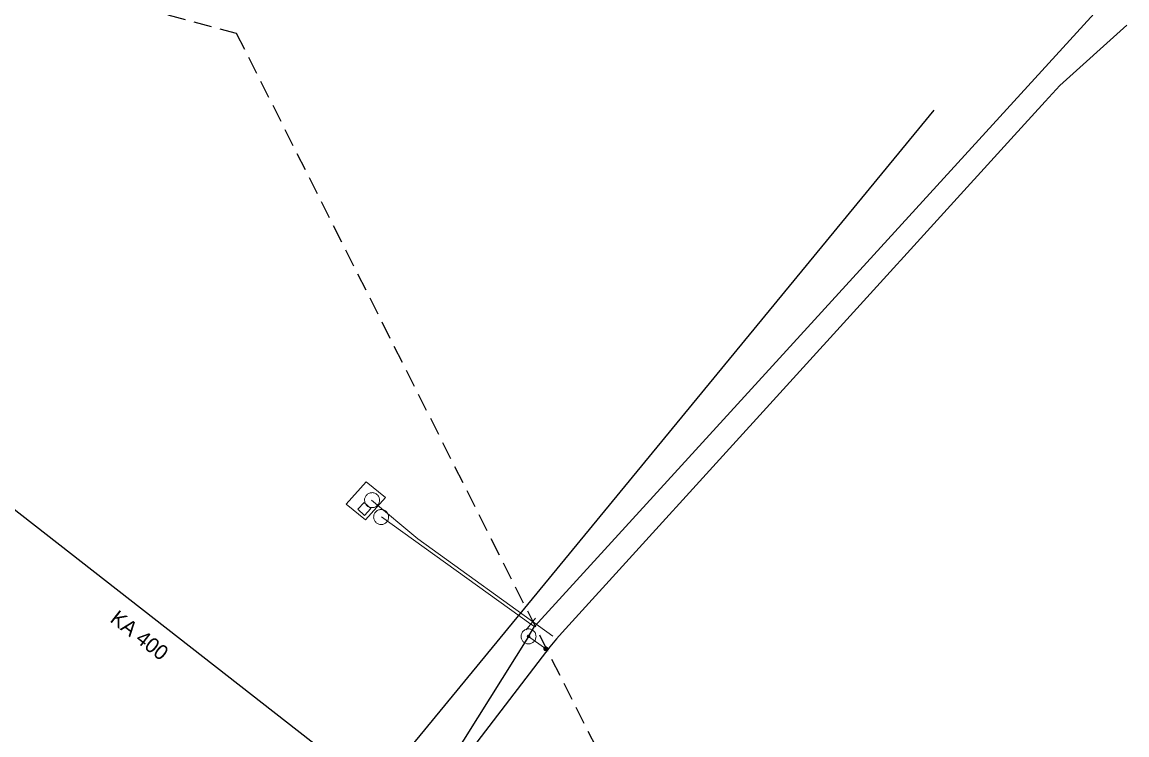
# Model space of a CAD drawing. Extents: x -790267 to -789874, y -989766 to -989454.
# Drawn here: x -789961.1 to -789887.3, y -989606.4 to -989558.8 of the extents above; entities that cross this region are included whole.
import ezdxf

# ---------------------------------------------------------------- set-up
doc = ezdxf.new("R2010")
doc.units = 0
doc.header["$LTSCALE"] = 0.4
doc.linetypes.add('MEDIUM_DASHED', pattern=[4.5, 3, -1.5])
doc.layers.add('1', color=7, linetype='Continuous')
for name, color, linetype, lineweight in [('13', 7, 'Continuous', 13), ('14', 7, 'Continuous', 13), ('17', 7, 'Continuous', 25), ('2', 7, 'Continuous', 13), ('23', 7, 'Continuous', 13), ('34', 7, 'Continuous', 13), ('47', 7, 'Continuous', 13), ('63', 7, 'MEDIUM_DASHED', 25), ('9', 7, 'Continuous', 13)]:
    doc.layers.add(name, color=color, linetype=linetype, lineweight=lineweight)

msp = doc.modelspace()

# ---------------------------------------------------------------- linework, layer by layer
at = {"layer": '13'}
msp.add_line((-789927.077, -989598.989), (-789937.049, -989591.839), dxfattribs=at)
msp.add_lwpolyline([(-789925.609, -989599.789), (-789934.62, -989593.289), (-789937.719, -989590.719)], dxfattribs=at)
at = {"layer": '14', "lineweight": 25}
for p, q in [((-789937.51, -989610.1), (-789900.16, -989564.68)), ((-789965.811, -989588.026), (-789937.51, -989610.1))]:
    msp.add_line(p, q, dxfattribs=at)
at = {"layer": '14'}
for p, q in [((-789926.833, -989599.162), (-789927.077, -989598.989)), ((-789927.239, -989599.813), (-789926.089, -989600.638))]:
    msp.add_line(p, q, dxfattribs=at)
at = {"layer": '17'}
msp.add_line((-789927.239, -989599.813), (-789932.749, -989608.579), dxfattribs=at)
for points in [[(-789927.239, -989599.813), (-789926.833, -989599.162), (-789888.3, -989556.917)], [(-789887.283, -989558.995), (-789891.77, -989563.02), (-789892.745, -989564.092), (-789895.041, -989566.616), (-789925, -989599.55), (-789925.366, -989599.978), (-789925.82, -989600.51), (-789931.5, -989607.92)]]:
    msp.add_lwpolyline(points, dxfattribs=at)
at = {"layer": '2'}
for points in [[(-789938.09, -989589.489), (-789939.42, -989590.98), (-789938.129, -989592.02), (-789936.794, -989590.53)], [(-789938.21, -989590.87), (-789938.629, -989591.309), (-789938.193, -989591.736), (-789937.76, -989591.28)]]:
    msp.add_lwpolyline(points, close=True, dxfattribs=at)
at = {"layer": '23'}
for points in [[(-789937.204, -989590.586), (-789937.219, -989590.537), (-789937.241, -989590.489), (-789937.266, -989590.444), (-789937.298, -989590.401), (-789937.333, -989590.363), (-789937.371, -989590.328), (-789937.414, -989590.298), (-789937.459, -989590.271), (-789937.507, -989590.249), (-789937.557, -989590.234), (-789937.608, -989590.222), (-789937.659, -989590.216), (-789937.712, -989590.218), (-789937.764, -989590.222), (-789937.815, -989590.233), (-789937.866, -989590.249), (-789937.913, -989590.27), (-789937.959, -989590.297), (-789938, -989590.328), (-789938.039, -989590.362), (-789938.075, -989590.401), (-789938.106, -989590.443), (-789938.132, -989590.489), (-789938.152, -989590.536), (-789938.169, -989590.586), (-789938.18, -989590.637), (-789938.185, -989590.69), (-789938.185, -989590.742), (-789938.179, -989590.793), (-789938.169, -989590.845), (-789938.153, -989590.894), (-789938.132, -989590.943), (-789938.105, -989590.989), (-789938.075, -989591.031), (-789938.04, -989591.068), (-789938.002, -989591.104), (-789937.958, -989591.135), (-789937.914, -989591.161), (-789937.864, -989591.183)], [(-789938.075, -989590.401), (-789938.106, -989590.443), (-789938.132, -989590.489), (-789938.152, -989590.536), (-789938.169, -989590.586), (-789938.18, -989590.637), (-789938.185, -989590.69), (-789938.185, -989590.742), (-789938.179, -989590.793), (-789938.169, -989590.845), (-789938.153, -989590.894), (-789938.132, -989590.943), (-789938.105, -989590.989), (-789938.075, -989591.031), (-789938.04, -989591.068), (-789938.002, -989591.104), (-789937.958, -989591.135), (-789937.914, -989591.161), (-789937.864, -989591.183), (-789937.817, -989591.199), (-789937.765, -989591.21), (-789937.712, -989591.215), (-789937.66, -989591.215), (-789937.607, -989591.209), (-789937.556, -989591.199), (-789937.507, -989591.183), (-789937.459, -989591.16), (-789937.414, -989591.135), (-789937.372, -989591.104), (-789937.333, -989591.068), (-789937.298, -989591.03), (-789937.267, -989590.988), (-789937.241, -989590.943), (-789937.219, -989590.894), (-789937.203, -989590.845), (-789937.193, -989590.795), (-789937.188, -989590.742), (-789937.187, -989590.69), (-789937.192, -989590.637), (-789937.204, -989590.586)], [(-789937.959, -989590.297), (-789938, -989590.328), (-789938.039, -989590.362), (-789938.075, -989590.401)], [(-789937.864, -989591.183), (-789937.817, -989591.199), (-789937.765, -989591.21), (-789937.712, -989591.215), (-789937.66, -989591.215), (-789937.607, -989591.209), (-789937.556, -989591.199), (-789937.507, -989591.183), (-789937.459, -989591.16), (-789937.414, -989591.135), (-789937.372, -989591.104), (-789937.333, -989591.068), (-789937.298, -989591.03), (-789937.267, -989590.988), (-789937.241, -989590.943), (-789937.219, -989590.894), (-789937.203, -989590.845), (-789937.193, -989590.795), (-789937.188, -989590.742), (-789937.187, -989590.69), (-789937.192, -989590.637), (-789937.204, -989590.586), (-789937.219, -989590.537), (-789937.241, -989590.489), (-789937.266, -989590.444), (-789937.298, -989590.401), (-789937.333, -989590.363), (-789937.371, -989590.328), (-789937.414, -989590.298), (-789937.459, -989590.271), (-789937.507, -989590.249), (-789937.557, -989590.234), (-789937.608, -989590.222), (-789937.659, -989590.216), (-789937.712, -989590.218), (-789937.764, -989590.222), (-789937.815, -989590.233), (-789937.866, -989590.249), (-789937.913, -989590.27), (-789937.959, -989590.297)], [(-789936.671, -989592.131), (-789936.643, -989592.086), (-789936.62, -989592.038), (-789936.603, -989591.99), (-789936.59, -989591.939), (-789936.583, -989591.888), (-789936.582, -989591.834), (-789936.585, -989591.783), (-789936.594, -989591.732), (-789936.608, -989591.681), (-789936.628, -989591.633), (-789936.652, -989591.586), (-789936.682, -989591.542), (-789936.715, -989591.502), (-789936.753, -989591.467), (-789936.793, -989591.434), (-789936.839, -989591.406), (-789936.885, -989591.383), (-789936.936, -989591.365), (-789936.984, -989591.352), (-789937.036, -989591.345), (-789937.09, -989591.344), (-789937.142, -989591.348), (-789937.194, -989591.357), (-789937.244, -989591.37), (-789937.292, -989591.39), (-789937.339, -989591.416), (-789937.381, -989591.444), (-789937.421, -989591.478), (-789937.457, -989591.516), (-789937.49, -989591.557), (-789937.518, -989591.601), (-789937.541, -989591.648), (-789937.559, -989591.698), (-789937.572, -989591.748), (-789937.578, -989591.799), (-789937.58, -989591.852), (-789937.577, -989591.904), (-789937.568, -989591.957), (-789937.553, -989592.007)], [(-789936.936, -989591.365), (-789936.984, -989591.352), (-789937.036, -989591.345), (-789937.09, -989591.344), (-789937.142, -989591.348), (-789937.194, -989591.357), (-789937.244, -989591.37), (-789937.292, -989591.39), (-789937.339, -989591.416), (-789937.381, -989591.444), (-789937.421, -989591.478), (-789937.457, -989591.516), (-789937.49, -989591.557), (-789937.518, -989591.601), (-789937.541, -989591.648), (-789937.559, -989591.698), (-789937.572, -989591.748), (-789937.578, -989591.799), (-789937.58, -989591.852), (-789937.577, -989591.904), (-789937.568, -989591.957), (-789937.553, -989592.007), (-789937.534, -989592.054), (-789937.509, -989592.101), (-789937.481, -989592.144), (-789937.445, -989592.184), (-789937.408, -989592.22), (-789937.368, -989592.253), (-789937.323, -989592.28), (-789937.276, -989592.303), (-789937.226, -989592.322), (-789937.176, -989592.334), (-789937.124, -989592.341), (-789937.072, -989592.344), (-789937.019, -989592.339), (-789936.968, -989592.331), (-789936.919, -989592.316), (-789936.869, -989592.297), (-789936.823, -989592.272), (-789936.779, -989592.242)], [(-789937.553, -989592.007), (-789937.534, -989592.054), (-789937.509, -989592.101), (-789937.481, -989592.144), (-789937.445, -989592.184), (-789937.408, -989592.22), (-789937.368, -989592.253), (-789937.323, -989592.28), (-789937.276, -989592.303), (-789937.226, -989592.322), (-789937.176, -989592.334), (-789937.124, -989592.341), (-789937.072, -989592.344), (-789937.019, -989592.339), (-789936.968, -989592.331), (-789936.919, -989592.316), (-789936.869, -989592.297), (-789936.823, -989592.272), (-789936.779, -989592.242), (-789936.74, -989592.208), (-789936.704, -989592.171), (-789936.671, -989592.131), (-789936.643, -989592.086), (-789936.62, -989592.038), (-789936.603, -989591.99), (-789936.59, -989591.939), (-789936.583, -989591.888), (-789936.582, -989591.834), (-789936.585, -989591.783), (-789936.594, -989591.732), (-789936.608, -989591.681), (-789936.628, -989591.633), (-789936.652, -989591.586), (-789936.682, -989591.542), (-789936.715, -989591.502), (-789936.753, -989591.467), (-789936.793, -989591.434), (-789936.839, -989591.406), (-789936.885, -989591.383), (-789936.936, -989591.365)], [(-789936.779, -989592.242), (-789936.74, -989592.208), (-789936.704, -989592.171), (-789936.671, -989592.131)]]:
    msp.add_lwpolyline(points, dxfattribs=at)
at = {"layer": '34'}
msp.add_line((-789926.768, -989598.595), (-789927.386, -989599.381), dxfattribs=at)
at = {"layer": '47'}
for points in [[(-789926.739, -989599.813), (-789926.742, -989599.761), (-789926.75, -989599.708), (-789926.764, -989599.659), (-789926.781, -989599.61), (-789926.806, -989599.563), (-789926.835, -989599.519), (-789926.867, -989599.478), (-789926.904, -989599.441), (-789926.945, -989599.409), (-789926.989, -989599.38), (-789927.036, -989599.355), (-789927.085, -989599.338), (-789927.134, -989599.324), (-789927.186, -989599.316), (-789927.239, -989599.313), (-789927.291, -989599.316), (-789927.343, -989599.324), (-789927.394, -989599.338), (-789927.441, -989599.355), (-789927.489, -989599.38), (-789927.532, -989599.409), (-789927.573, -989599.441), (-789927.61, -989599.478), (-789927.644, -989599.519), (-789927.671, -989599.563), (-789927.696, -989599.61), (-789927.715, -989599.659), (-789927.727, -989599.708), (-789927.735, -989599.761), (-789927.739, -989599.813), (-789927.735, -989599.865), (-789927.727, -989599.917), (-789927.715, -989599.968), (-789927.696, -989600.016), (-789927.671, -989600.063), (-789927.644, -989600.107), (-789927.61, -989600.147), (-789927.573, -989600.184), (-789927.532, -989600.218), (-789927.489, -989600.245), (-789927.441, -989600.27), (-789927.394, -989600.289), (-789927.343, -989600.301), (-789927.291, -989600.309), (-789927.239, -989600.313), (-789927.186, -989600.309), (-789927.134, -989600.301), (-789927.085, -989600.289), (-789927.036, -989600.27), (-789926.989, -989600.245), (-789926.945, -989600.218), (-789926.904, -989600.184), (-789926.867, -989600.147), (-789926.835, -989600.107), (-789926.806, -989600.063), (-789926.781, -989600.016), (-789926.764, -989599.968), (-789926.75, -989599.917), (-789926.742, -989599.865)], [(-789927.156, -989599.813), (-789927.156, -989599.804), (-789927.159, -989599.796), (-789927.161, -989599.788), (-789927.164, -989599.779), (-789927.168, -989599.772), (-789927.173, -989599.765), (-789927.178, -989599.757), (-789927.183, -989599.752), (-789927.191, -989599.747), (-789927.198, -989599.742), (-789927.205, -989599.738), (-789927.213, -989599.735), (-789927.222, -989599.733), (-789927.23, -989599.73), (-789927.239, -989599.73), (-789927.247, -989599.73), (-789927.255, -989599.733), (-789927.264, -989599.735), (-789927.272, -989599.738), (-789927.279, -989599.742), (-789927.286, -989599.747), (-789927.294, -989599.752), (-789927.299, -989599.757), (-789927.306, -989599.765), (-789927.309, -989599.772), (-789927.313, -989599.779), (-789927.316, -989599.788), (-789927.318, -989599.796), (-789927.321, -989599.804), (-789927.321, -989599.813), (-789927.321, -989599.821), (-789927.318, -989599.83), (-789927.316, -989599.838), (-789927.313, -989599.846), (-789927.309, -989599.853), (-789927.306, -989599.86), (-789927.299, -989599.868), (-789927.294, -989599.874), (-789927.286, -989599.88), (-789927.279, -989599.884), (-789927.272, -989599.887), (-789927.264, -989599.891), (-789927.255, -989599.892), (-789927.247, -989599.895), (-789927.239, -989599.895), (-789927.23, -989599.895), (-789927.222, -989599.892), (-789927.213, -989599.891), (-789927.205, -989599.887), (-789927.198, -989599.884), (-789927.191, -989599.88), (-789927.183, -989599.874), (-789927.178, -989599.868), (-789927.173, -989599.86), (-789927.168, -989599.853), (-789927.164, -989599.846), (-789927.161, -989599.838), (-789927.159, -989599.83), (-789927.156, -989599.821)]]:
    msp.add_lwpolyline(points, close=True, dxfattribs=at)
at = {"layer": '63'}
msp.add_lwpolyline([(-790188.469, -989455.136), (-790139.344, -989496.446), (-790139.344, -989496.446), (-790029.929, -989518.217), (-790029.929, -989518.217), (-789963.498, -989555.061), (-789963.498, -989555.061), (-789946.75, -989559.527), (-789946.75, -989559.527), (-789908.79, -989634.89), (-789908.79, -989634.89), (-790051.142, -989765.519), (-790051.142, -989765.519), (-790157.208, -989714.719), (-790157.208, -989714.719), (-790153.3, -989672.851), (-790153.3, -989672.851), (-790266.065, -989576.274), (-790266.065, -989576.274), (-790235.362, -989502.586), (-790235.362, -989502.586), (-790189.028, -989455.694), (-790189.028, -989455.694)], close=True, dxfattribs=at)
at = {"layer": '9'}
for points in [[(-789926.215, -989600.638), (-789926.215, -989600.651), (-789926.213, -989600.664), (-789926.21, -989600.677), (-789926.205, -989600.689), (-789926.199, -989600.701), (-789926.192, -989600.712), (-789926.184, -989600.722), (-789926.174, -989600.732), (-789926.164, -989600.74), (-789926.153, -989600.747), (-789926.141, -989600.753), (-789926.129, -989600.758), (-789926.116, -989600.761), (-789926.103, -989600.763), (-789926.09, -989600.765), (-789926.077, -989600.764), (-789926.064, -989600.762), (-789926.051, -989600.759), (-789926.039, -989600.754), (-789926.027, -989600.748), (-789926.016, -989600.741), (-789926.006, -989600.733), (-789925.996, -989600.723), (-789925.988, -989600.713), (-789925.981, -989600.702), (-789925.975, -989600.69), (-789925.97, -989600.678), (-789925.967, -989600.665), (-789925.965, -989600.652), (-789925.963, -989600.639), (-789925.964, -989600.626), (-789925.966, -989600.613), (-789925.969, -989600.6), (-789925.974, -989600.588), (-789925.98, -989600.576), (-789925.987, -989600.565), (-789925.995, -989600.555), (-789926.005, -989600.545), (-789926.015, -989600.537), (-789926.026, -989600.53), (-789926.038, -989600.524), (-789926.05, -989600.519), (-789926.063, -989600.516), (-789926.076, -989600.514), (-789926.089, -989600.513), (-789926.102, -989600.513), (-789926.115, -989600.515), (-789926.128, -989600.518), (-789926.14, -989600.523), (-789926.152, -989600.529), (-789926.163, -989600.536), (-789926.173, -989600.544), (-789926.183, -989600.554), (-789926.191, -989600.564), (-789926.198, -989600.575), (-789926.204, -989600.587), (-789926.209, -989600.599), (-789926.212, -989600.612), (-789926.214, -989600.625)], [(-789926.195, -989600.638), (-789926.196, -989600.649), (-789926.194, -989600.66), (-789926.191, -989600.671), (-789926.187, -989600.681), (-789926.182, -989600.691), (-789926.176, -989600.7), (-789926.169, -989600.709), (-789926.161, -989600.717), (-789926.152, -989600.724), (-789926.143, -989600.73), (-789926.133, -989600.735), (-789926.123, -989600.739), (-789926.112, -989600.742), (-789926.101, -989600.745), (-789926.09, -989600.745), (-789926.079, -989600.745), (-789926.068, -989600.743), (-789926.057, -989600.74), (-789926.047, -989600.736), (-789926.037, -989600.731), (-789926.028, -989600.725), (-789926.019, -989600.718), (-789926.011, -989600.71), (-789926.004, -989600.701), (-789925.998, -989600.692), (-789925.993, -989600.682), (-789925.989, -989600.672), (-789925.986, -989600.661), (-789925.984, -989600.65), (-789925.983, -989600.639), (-789925.983, -989600.628), (-789925.985, -989600.617), (-789925.988, -989600.606), (-789925.992, -989600.596), (-789925.997, -989600.586), (-789926.003, -989600.577), (-789926.01, -989600.568), (-789926.018, -989600.56), (-789926.027, -989600.553), (-789926.036, -989600.547), (-789926.046, -989600.542), (-789926.056, -989600.538), (-789926.067, -989600.535), (-789926.078, -989600.533), (-789926.089, -989600.533), (-789926.1, -989600.532), (-789926.111, -989600.534), (-789926.122, -989600.537), (-789926.132, -989600.541), (-789926.142, -989600.546), (-789926.151, -989600.552), (-789926.16, -989600.559), (-789926.168, -989600.567), (-789926.175, -989600.576), (-789926.181, -989600.585), (-789926.186, -989600.595), (-789926.19, -989600.605), (-789926.193, -989600.616), (-789926.195, -989600.627)], [(-789926.176, -989600.638), (-789926.176, -989600.647), (-789926.175, -989600.656), (-789926.172, -989600.665), (-789926.169, -989600.673), (-789926.165, -989600.681), (-789926.16, -989600.689), (-789926.154, -989600.696), (-789926.148, -989600.702), (-789926.141, -989600.708), (-789926.133, -989600.713), (-789926.125, -989600.717), (-789926.117, -989600.72), (-789926.108, -989600.723), (-789926.099, -989600.724), (-789926.09, -989600.726), (-789926.081, -989600.725), (-789926.072, -989600.724), (-789926.063, -989600.721), (-789926.055, -989600.718), (-789926.047, -989600.714), (-789926.039, -989600.709), (-789926.032, -989600.703), (-789926.026, -989600.697), (-789926.02, -989600.69), (-789926.015, -989600.682), (-789926.011, -989600.674), (-789926.008, -989600.666), (-789926.005, -989600.657), (-789926.004, -989600.648), (-789926.002, -989600.639), (-789926.003, -989600.63), (-789926.004, -989600.621), (-789926.007, -989600.612), (-789926.01, -989600.604), (-789926.014, -989600.596), (-789926.019, -989600.588), (-789926.025, -989600.581), (-789926.031, -989600.575), (-789926.038, -989600.569), (-789926.046, -989600.564), (-789926.054, -989600.56), (-789926.062, -989600.557), (-789926.071, -989600.554), (-789926.08, -989600.553), (-789926.089, -989600.552), (-789926.098, -989600.552), (-789926.107, -989600.553), (-789926.116, -989600.556), (-789926.124, -989600.559), (-789926.132, -989600.563), (-789926.14, -989600.568), (-789926.147, -989600.574), (-789926.153, -989600.58), (-789926.159, -989600.587), (-789926.164, -989600.595), (-789926.168, -989600.603), (-789926.171, -989600.611), (-789926.174, -989600.62), (-789926.175, -989600.629)], [(-789926.156, -989600.638), (-789926.156, -989600.645), (-789926.155, -989600.652), (-789926.154, -989600.659), (-789926.151, -989600.665), (-789926.148, -989600.671), (-789926.144, -989600.677), (-789926.14, -989600.683), (-789926.135, -989600.688), (-789926.129, -989600.692), (-789926.123, -989600.696), (-789926.117, -989600.699), (-789926.111, -989600.702), (-789926.104, -989600.703), (-789926.097, -989600.706), (-789926.09, -989600.706), (-789926.083, -989600.706), (-789926.076, -989600.704), (-789926.069, -989600.703), (-789926.063, -989600.7), (-789926.056, -989600.697), (-789926.051, -989600.693), (-789926.045, -989600.689), (-789926.04, -989600.684), (-789926.036, -989600.678), (-789926.032, -989600.672), (-789926.029, -989600.666), (-789926.026, -989600.66), (-789926.024, -989600.653), (-789926.023, -989600.646), (-789926.022, -989600.639), (-789926.022, -989600.632), (-789926.023, -989600.625), (-789926.025, -989600.618), (-789926.028, -989600.612), (-789926.031, -989600.605), (-789926.035, -989600.6), (-789926.039, -989600.594), (-789926.044, -989600.589), (-789926.05, -989600.585), (-789926.055, -989600.581), (-789926.062, -989600.578), (-789926.068, -989600.575), (-789926.075, -989600.573), (-789926.082, -989600.572), (-789926.089, -989600.572), (-789926.096, -989600.572), (-789926.103, -989600.572), (-789926.11, -989600.574), (-789926.116, -989600.577), (-789926.122, -989600.58), (-789926.128, -989600.584), (-789926.134, -989600.588), (-789926.139, -989600.593), (-789926.143, -989600.599), (-789926.147, -989600.604), (-789926.15, -989600.611), (-789926.153, -989600.617), (-789926.154, -989600.624), (-789926.156, -989600.631)], [(-789926.136, -989600.638), (-789926.136, -989600.643), (-789926.136, -989600.648), (-789926.135, -989600.653), (-789926.133, -989600.657), (-789926.131, -989600.662), (-789926.128, -989600.666), (-789926.125, -989600.669), (-789926.121, -989600.673), (-789926.118, -989600.676), (-789926.114, -989600.679), (-789926.109, -989600.681), (-789926.105, -989600.683), (-789926.1, -989600.684), (-789926.095, -989600.686), (-789926.09, -989600.686), (-789926.085, -989600.686), (-789926.08, -989600.685), (-789926.075, -989600.684), (-789926.071, -989600.682), (-789926.066, -989600.68), (-789926.062, -989600.677), (-789926.058, -989600.674), (-789926.055, -989600.67), (-789926.052, -989600.667), (-789926.049, -989600.663), (-789926.047, -989600.658), (-789926.045, -989600.654), (-789926.044, -989600.649), (-789926.043, -989600.644), (-789926.042, -989600.639), (-789926.042, -989600.634), (-789926.043, -989600.629), (-789926.044, -989600.624), (-789926.046, -989600.62), (-789926.048, -989600.615), (-789926.051, -989600.611), (-789926.054, -989600.607), (-789926.057, -989600.604), (-789926.061, -989600.601), (-789926.065, -989600.598), (-789926.07, -989600.596), (-789926.074, -989600.594), (-789926.079, -989600.593), (-789926.084, -989600.592), (-789926.089, -989600.592), (-789926.094, -989600.592), (-789926.099, -989600.593), (-789926.104, -989600.593), (-789926.108, -989600.595), (-789926.113, -989600.597), (-789926.117, -989600.6), (-789926.12, -989600.603), (-789926.124, -989600.606), (-789926.127, -989600.61), (-789926.13, -989600.614), (-789926.132, -989600.619), (-789926.134, -989600.623), (-789926.135, -989600.628), (-789926.136, -989600.633)], [(-789926.116, -989600.638), (-789926.116, -989600.641), (-789926.117, -989600.644), (-789926.116, -989600.646), (-789926.115, -989600.649), (-789926.114, -989600.652), (-789926.112, -989600.654), (-789926.11, -989600.656), (-789926.108, -989600.658), (-789926.106, -989600.66), (-789926.104, -989600.662), (-789926.101, -989600.664), (-789926.098, -989600.665), (-789926.096, -989600.665), (-789926.093, -989600.666), (-789926.09, -989600.666), (-789926.087, -989600.666), (-789926.084, -989600.666), (-789926.081, -989600.665), (-789926.079, -989600.664), (-789926.076, -989600.663), (-789926.074, -989600.661), (-789926.071, -989600.659), (-789926.069, -989600.657), (-789926.068, -989600.655), (-789926.066, -989600.653), (-789926.065, -989600.65), (-789926.063, -989600.647), (-789926.063, -989600.645), (-789926.062, -989600.642), (-789926.061, -989600.639), (-789926.062, -989600.636), (-789926.062, -989600.633), (-789926.063, -989600.63), (-789926.064, -989600.628), (-789926.065, -989600.625), (-789926.067, -989600.623), (-789926.068, -989600.62), (-789926.07, -989600.618), (-789926.073, -989600.617), (-789926.075, -989600.615), (-789926.078, -989600.614), (-789926.08, -989600.613), (-789926.083, -989600.612), (-789926.086, -989600.612), (-789926.089, -989600.611), (-789926.092, -989600.612), (-789926.095, -989600.611), (-789926.097, -989600.613), (-789926.1, -989600.613), (-789926.103, -989600.614), (-789926.105, -989600.616), (-789926.107, -989600.617), (-789926.109, -989600.619), (-789926.111, -989600.622), (-789926.113, -989600.624), (-789926.114, -989600.627), (-789926.115, -989600.629), (-789926.116, -989600.632), (-789926.116, -989600.635)], [(-789926.097, -989600.638), (-789926.097, -989600.64), (-789926.097, -989600.64), (-789926.096, -989600.64), (-789926.096, -989600.642), (-789926.097, -989600.643), (-789926.095, -989600.643), (-789926.095, -989600.643), (-789926.095, -989600.645), (-789926.095, -989600.645), (-789926.094, -989600.646), (-789926.092, -989600.646), (-789926.092, -989600.646), (-789926.092, -989600.647), (-789926.09, -989600.647), (-789926.09, -989600.647), (-789926.089, -989600.647), (-789926.088, -989600.647), (-789926.088, -989600.646), (-789926.087, -989600.646), (-789926.085, -989600.646), (-789926.085, -989600.645), (-789926.085, -989600.645), (-789926.084, -989600.644), (-789926.084, -989600.644), (-789926.082, -989600.643), (-789926.082, -989600.642), (-789926.081, -989600.641), (-789926.081, -989600.641), (-789926.081, -989600.64), (-789926.081, -989600.639), (-789926.081, -989600.638), (-789926.081, -989600.637), (-789926.081, -989600.637), (-789926.082, -989600.636), (-789926.082, -989600.635), (-789926.083, -989600.634), (-789926.083, -989600.634), (-789926.084, -989600.633), (-789926.084, -989600.633), (-789926.085, -989600.632), (-789926.086, -989600.632), (-789926.087, -989600.631), (-789926.087, -989600.631), (-789926.088, -989600.631), (-789926.089, -989600.631), (-789926.09, -989600.631), (-789926.091, -989600.631), (-789926.091, -989600.631), (-789926.092, -989600.632), (-789926.093, -989600.631), (-789926.094, -989600.633), (-789926.094, -989600.633), (-789926.095, -989600.633), (-789926.095, -989600.633), (-789926.096, -989600.635), (-789926.096, -989600.636), (-789926.096, -989600.637), (-789926.097, -989600.637), (-789926.097, -989600.638)]]:
    msp.add_lwpolyline(points, close=True, dxfattribs=at)

# ---------------------------------------------------------------- texts
at = {"layer": '1'}
msp.add_text('KA 400', height=1, rotation=322, dxfattribs=at).set_placement((-789955.247, -989598.783))

doc.saveas('drawing.dxf')
